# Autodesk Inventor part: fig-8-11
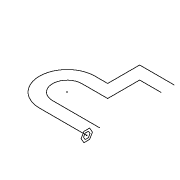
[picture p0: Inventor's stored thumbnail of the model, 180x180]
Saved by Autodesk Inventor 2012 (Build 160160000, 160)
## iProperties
Created: 2004-05
Part Number: fig-8-11
Document SubType Name: Modeling
Designer: CADCIM Technologies
Manufacturer: Standard
Standards Organization: Custom
Density: 1 g/cm^3
Material: Default
Author: CADCIM Technologies
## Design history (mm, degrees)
sketch "Sketch1"
  geometry: L1 (-42.583, 3.219)-(-90.066, 3.219); L2 (-90.066, 58.92)-(-77.282, 58.92); L3 (-77.282, 58.92)-(-77.282, 91.063); L4 (-77.282, 91.063)-(-42.583, 91.063); L5 (-42.583, 77.975)-(-64.194, 77.975); L6 (-64.194, 77.975)-(-64.194, 45.833); L7 (-64.194, 45.833)-(-90.066, 45.833); L8 (-90.066, 16.307)-(-42.583, 16.307); A1 r 27.851 centre (-90.066, 31.07) between (-90.066, 58.92) and (-90.066, 3.219); A2 r 14.763 centre (-90.066, 31.07) between (-90.066, 45.833) and (-90.066, 16.307)
  constraints: 16 end point, 4 parallel, 4 point on circle, 2 centre point, 2 perpendicular, 2 tangent, 4 other
workplane "Work Plane2"
sketch "Sketch2"
  geometry: L1 (-5.697, 0)-(-2.849, 4.934); L2 (-2.849, 4.934)-(2.849, 4.934); L3 (2.849, 4.934)-(5.697, 0); L4 (5.697, 0)-(2.849, -4.934); L5 (2.849, -4.934)-(-2.849, -4.934); L6 (-2.849, -4.934)-(-5.697, 0); L7 (-3.256, 0)-(-1.628, 2.819); L8 (-1.628, 2.819)-(1.628, 2.819); L9 (1.628, 2.819)-(3.256, 0); L10 (3.256, 0)-(1.628, -2.819); L11 (1.628, -2.819)-(-1.628, -2.819); L12 (-1.628, -2.819)-(-3.256, 0); 2 further points
  constraints: 24 end point, 1 coincident, 22 other
